Omron CX-Programmer project NewProject (CX-Programmer 6.11)

# PLC Elevator: CPM1(CPM1A) CPU20

## Global symbols (name address type ; comment)
Button_1 200.07 BOOL  ; Call Button 1st
Button_2 200.06 BOOL  ; Call Button 2nd
Button_3 200.05 BOOL  ; Call Button 3rd
Button_4 200.04 BOOL  ; Call Button 4th
Button_Dn 200.09 BOOL  ; Manual Down
Button_Up 200.08 BOOL  ; Manual Up
Fault_Initialize 211.00 BOOL  ; Fault - Initialize
Fault_Motor_Down 211.02 BOOL  ; Fault - Motor Down
Fault_Motor_Up 211.01 BOOL  ; Fault - Motor Up
Fault_Reset_Bit 208.00 BOOL  ; Fault Reset Bit
Floor_Number 220 CHANNEL  ; Current Floor Number
HMI_IO_PC 232 CHANNEL L  ; HMI IO From SCADA (PC)
HMI_IO_PLC 231 CHANNEL L  ; HMI IO From PLC
HMI_I_BTN1 233.00 BOOL L  ; HMI SCADA - 1st Floor Button
HMI_I_BTN2 233.01 BOOL L  ; HMI SCADA - 2nd Floor Button
HMI_I_BTN3 233.02 BOOL L  ; HMI SCADA - 3rd Floor Button
HMI_I_BTN4 233.03 BOOL L  ; HMI SCADA - 4th Floor Button
HMI_I_MAND 233.05 BOOL L  ; HMI SCADA - Manual Down Button
HMI_I_MANU 233.04 BOOL L  ; HMI SCADA - Manual Up Button
HMI_O_Down 233.07 BOOL L  ; HMI SCADA - Down Motor Running
HMI_O_Up 233.06 BOOL L  ; HMI SCADA - Up Motor Running
HMI_Step 230 CHANNEL L  ; HMI Step String
I_00 0.00 BOOL  ; GN Start - 4th
I_01 0.01 BOOL  ; BK Start - 3rd
I_02 0.02 BOOL  ; BK Jog - 2nd
I_03 0.03 BOOL  ; RD EStop - 1st
I_04 0.04 BOOL  ; RD Stop - UP
I_05 0.05 BOOL  ; RD Stop - DN
I_07 0.07 BOOL  ; Basement
I_08 0.08 BOOL  ; Level 1
I_09 0.09 BOOL  ; Level 4
I_10 0.10 BOOL  ; Level 3
I_11 0.11 BOOL  ; Level 2
LS_Basement 200.10 BOOL  ; Elevator @ Basement
LS_Level1 200.00 BOOL  ; Elevator @ Level 1
LS_Level2 200.01 BOOL  ; Elevator @ Level 2
LS_Level3 200.02 BOOL  ; Elevator @ Level 3
LS_Level4 200.03 BOOL  ; Elevator @ Level 4
O_01 10.01 BOOL  ; Up Motor
O_02 10.02 BOOL  ; Down Motor
Req_Floor 221 CHANNEL  ; Request Floor
Run_Motor_Down_15 210.03 BOOL  ; Run Down Motor (S15)
Run_Motor_Down_2 210.01 BOOL  ; Run Down Motor (S2)
Run_Motor_Down_30 210.05 BOOL  ; Run Down Motor (S30)
Run_Motor_Up_12 210.00 BOOL  ; Run Up Motor (S12)
Run_Motor_Up_20 210.02 BOOL  ; Run Up Motor (S20)
S_02 202.00 BOOL  ; Step S02
S_03 202.01 BOOL  ; Step S03
S_04 202.02 BOOL  ; Step S04
S_05 202.03 BOOL  ; Step S05
S_06 202.04 BOOL  ; Step S06
S_07 202.05 BOOL  ; Step S07
S_10 202.06 BOOL  ; Step S10
S_11 202.07 BOOL  ; Step S11
S_120 202.08 BOOL  ; Step S120
S_121 202.09 BOOL  ; Step S121
S_122 202.10 BOOL  ; Step S122
S_123 202.11 BOOL  ; Step S123
S_124 202.12 BOOL  ; Step S124
S_150 204.05 BOOL  ; Step S150
S_151 204.06 BOOL  ; Step S151
S_152 204.07 BOOL  ; Step S152
S_153 204.08 BOOL  ; Step S153
S_154 204.09 BOOL  ; Step S154
S_20 204.02 BOOL  ; Step S20
S_30 204.03 BOOL  ; Step S30
S_60 206.00 BOOL  ; Initialize Fault Timer
S_65 206.01 BOOL  ; Motor Up Fault Timer
S_70 206.02 BOOL  ; Motor Down Fault Timer
S_75 206.03 BOOL  ; Manual Up Fault Timer
S_80 206.04 BOOL  ; Manual Down Fault Timer
T_00 201.00 BOOL  ; Transition T00
T_02A 201.01 BOOL  ; Transition T02A
T_02B 201.02 BOOL  ; Transition T02B
T_02C 201.03 BOOL  ; Transition T02C
T_02D 201.04 BOOL  ; Transition T02D
T_02E 201.05 BOOL  ; Transition T02E
T_02F 201.06 BOOL  ; Transition T02F
T_03A 201.07 BOOL  ; Transition T03A
T_03B 201.08 BOOL  ; Transition T03B
T_03C 201.09 BOOL  ; Transition T03C
T_03D 201.10 BOOL  ; Transition T03D
T_03E 201.11 BOOL  ; Transition T03E
T_10A 203.00 BOOL  ; Transition T10A
T_10B 203.01 BOOL  ; Transition T10B
T_10C 203.02 BOOL  ; Transition T10C
T_11A 203.03 BOOL  ; Transition T11A
T_11B 203.04 BOOL  ; Transition T11B
T_12 203.05 BOOL  ; Transition T12
T_12A 203.06 BOOL  ; Transition T12A
T_12A1 203.07 BOOL  ; Transition T12A1
T_12B 203.08 BOOL  ; Transition T12B
T_12B1 203.09 BOOL  ; Transition T12B1
T_12C 203.10 BOOL  ; Transition T12C
T_12C1 203.11 BOOL  ; Transition T12C1
T_12D 203.12 BOOL  ; Transition T12D
T_12D1 203.13 BOOL  ; Transition T12D1
T_12E 203.14 BOOL  ; Transition T12E
T_15 209.00 BOOL  ; Transition T15
T_15A 209.01 BOOL  ; Transition T15A
T_15A1 209.02 BOOL  ; Transition T15A1
T_15B 209.03 BOOL  ; Transition T15B
T_15B1 209.04 BOOL  ; Transition T15B1
T_15C 209.05 BOOL  ; Transition T15C
T_15C1 209.06 BOOL  ; Transition T15C1
T_15D 209.07 BOOL  ; Transition T15D
T_15D1 209.08 BOOL  ; Transition T15D1
T_15E 209.09 BOOL  ; Transition T15E
T_20A 205.00 BOOL  ; Transition T20A
T_20B 205.01 BOOL  ; Transition T20B
T_20C 205.02 BOOL  ; Transition T20C
T_20D 205.03 BOOL  ; Transition T20D
T_20E 205.04 BOOL  ; Transition T20E
T_30A 205.05 BOOL  ; Transition T30A
T_30B 205.06 BOOL  ; Transition T30B
T_30C 205.07 BOOL  ; Transition T30C
T_30D 205.08 BOOL  ; Transition T30D
T_30E 205.09 BOOL  ; Transition T30E
T_60 207.00 BOOL  ; Transition T60
T_65 207.01 BOOL  ; Transition T65
T_70 207.02 BOOL  ; Transition T70
T_75 207.03 BOOL  ; Transition T75
T_80 207.04 BOOL  ; Transition T80
Timer_Flt_Dn TIM003 BOOL  ; Motor Down Fault
Timer_Flt_Init TIM001 BOOL  ; Initialization Fault Timer
Timer_Flt_Man_Down TIM006 BOOL  ; Manual Down Fault
Timer_Flt_Man_Up TIM004 BOOL  ; Manual Up Fault
Timer_Flt_Up TIM002 BOOL  ; Motor Up Fault
Timer_Running20 TIM005 BOOL  ; Running Timer (S20)
Timer_Running30 TIM007 BOOL  ; Running Timer (S30)

## Program Elevator (no task)

### Section Transistions

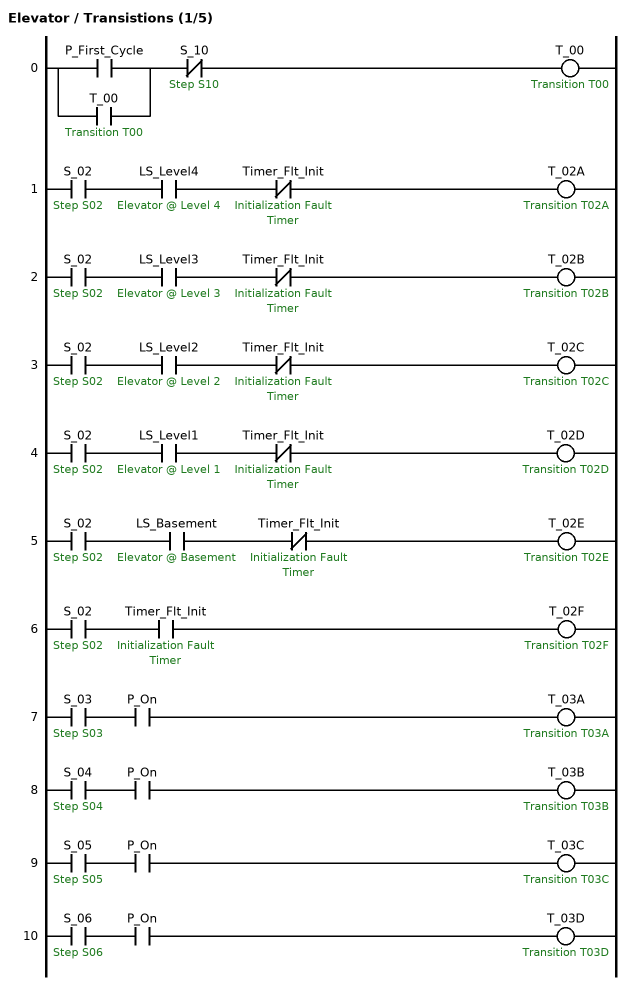
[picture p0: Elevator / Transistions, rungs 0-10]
; rung 0
LD P_First_Cycle
OR T_00  ; Transition T00
ANDNOT S_10  ; Step S10
OUT T_00  ; Transition T00
; rung 1
LD S_02  ; Step S02
AND LS_Level4  ; Elevator @ Level 4
ANDNOT Timer_Flt_Init  ; Initialization Fault Timer
OUT T_02A  ; Transition T02A
; rung 2
LD S_02  ; Step S02
AND LS_Level3  ; Elevator @ Level 3
ANDNOT Timer_Flt_Init  ; Initialization Fault Timer
OUT T_02B  ; Transition T02B
; rung 3
LD S_02  ; Step S02
AND LS_Level2  ; Elevator @ Level 2
ANDNOT Timer_Flt_Init  ; Initialization Fault Timer
OUT T_02C  ; Transition T02C
; rung 4
LD S_02  ; Step S02
AND LS_Level1  ; Elevator @ Level 1
ANDNOT Timer_Flt_Init  ; Initialization Fault Timer
OUT T_02D  ; Transition T02D
; rung 5
LD S_02  ; Step S02
AND LS_Basement  ; Elevator @ Basement
ANDNOT Timer_Flt_Init  ; Initialization Fault Timer
OUT T_02E  ; Transition T02E
; rung 6
LD S_02  ; Step S02
AND Timer_Flt_Init  ; Initialization Fault Timer
OUT T_02F  ; Transition T02F
; rung 7
LD S_03  ; Step S03
AND P_On
OUT T_03A  ; Transition T03A
; rung 8
LD S_04  ; Step S04
AND P_On
OUT T_03B  ; Transition T03B
; rung 9
LD S_05  ; Step S05
AND P_On
OUT T_03C  ; Transition T03C
; rung 10
LD S_06  ; Step S06
AND P_On
OUT T_03D  ; Transition T03D

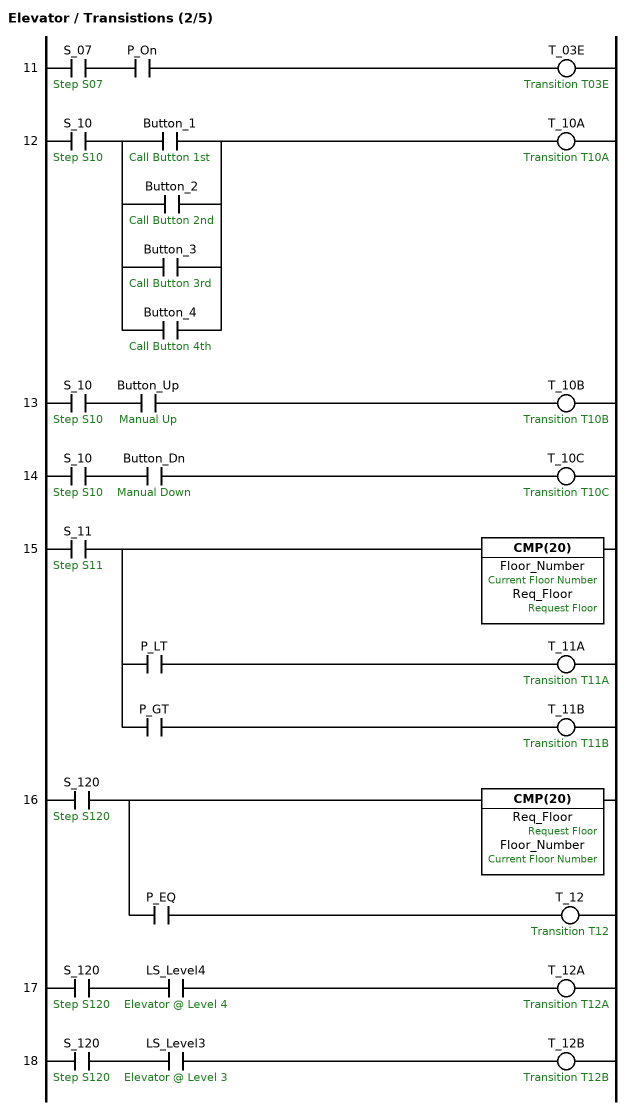
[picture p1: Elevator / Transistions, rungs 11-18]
; rung 11
LD S_07  ; Step S07
AND P_On
OUT T_03E  ; Transition T03E
; rung 12
LD S_10  ; Step S10
LD Button_1  ; Call Button 1st
OR Button_2  ; Call Button 2nd
OR Button_3  ; Call Button 3rd
OR Button_4  ; Call Button 4th
ANDLD
OUT T_10A  ; Transition T10A
; rung 13
LD S_10  ; Step S10
AND Button_Up  ; Manual Up
OUT T_10B  ; Transition T10B
; rung 14
LD S_10  ; Step S10
AND Button_Dn  ; Manual Down
OUT T_10C  ; Transition T10C
; rung 15
LD S_11  ; Step S11
OUT TR0
CMP(20) Floor_Number Req_Floor  ; Current Floor Number, Request Floor
AND P_LT
OUT T_11A  ; Transition T11A
LD TR0
AND P_GT
OUT T_11B  ; Transition T11B
; rung 16
LD S_120  ; Step S120
CMP(20) Req_Floor Floor_Number  ; Request Floor, Current Floor Number
AND P_EQ
OUT T_12  ; Transition T12
; rung 17
LD S_120  ; Step S120
AND LS_Level4  ; Elevator @ Level 4
OUT T_12A  ; Transition T12A
; rung 18
LD S_120  ; Step S120
AND LS_Level3  ; Elevator @ Level 3
OUT T_12B  ; Transition T12B

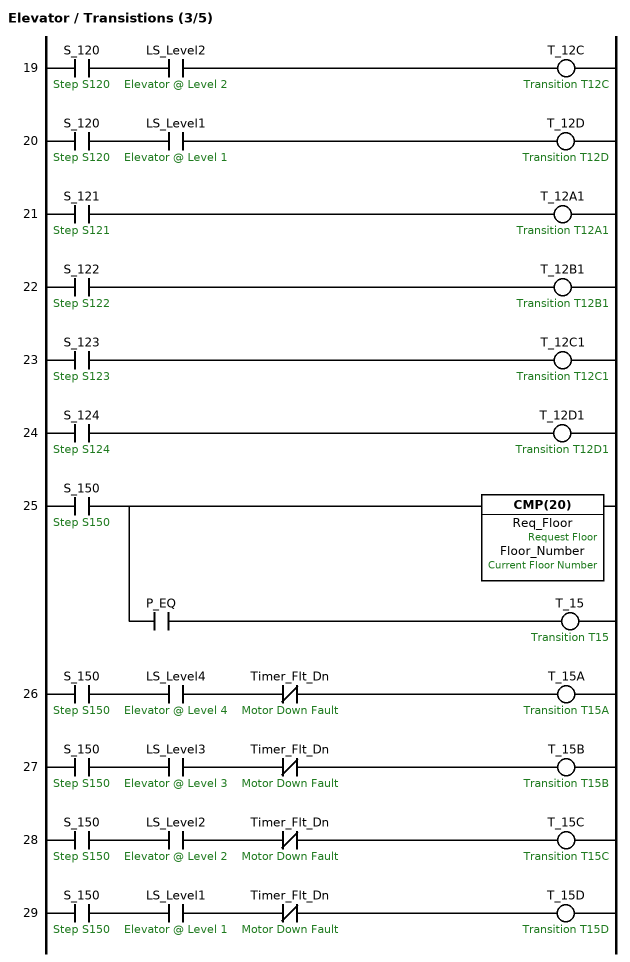
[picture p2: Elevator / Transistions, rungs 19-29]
; rung 19
LD S_120  ; Step S120
AND LS_Level2  ; Elevator @ Level 2
OUT T_12C  ; Transition T12C
; rung 20
LD S_120  ; Step S120
AND LS_Level1  ; Elevator @ Level 1
OUT T_12D  ; Transition T12D
; rung 21
LD S_121  ; Step S121
OUT T_12A1  ; Transition T12A1
; rung 22
LD S_122  ; Step S122
OUT T_12B1  ; Transition T12B1
; rung 23
LD S_123  ; Step S123
OUT T_12C1  ; Transition T12C1
; rung 24
LD S_124  ; Step S124
OUT T_12D1  ; Transition T12D1
; rung 25
LD S_150  ; Step S150
CMP(20) Req_Floor Floor_Number  ; Request Floor, Current Floor Number
AND P_EQ
OUT T_15  ; Transition T15
; rung 26
LD S_150  ; Step S150
AND LS_Level4  ; Elevator @ Level 4
ANDNOT Timer_Flt_Dn  ; Motor Down Fault
OUT T_15A  ; Transition T15A
; rung 27
LD S_150  ; Step S150
AND LS_Level3  ; Elevator @ Level 3
ANDNOT Timer_Flt_Dn  ; Motor Down Fault
OUT T_15B  ; Transition T15B
; rung 28
LD S_150  ; Step S150
AND LS_Level2  ; Elevator @ Level 2
ANDNOT Timer_Flt_Dn  ; Motor Down Fault
OUT T_15C  ; Transition T15C
; rung 29
LD S_150  ; Step S150
AND LS_Level1  ; Elevator @ Level 1
ANDNOT Timer_Flt_Dn  ; Motor Down Fault
OUT T_15D  ; Transition T15D

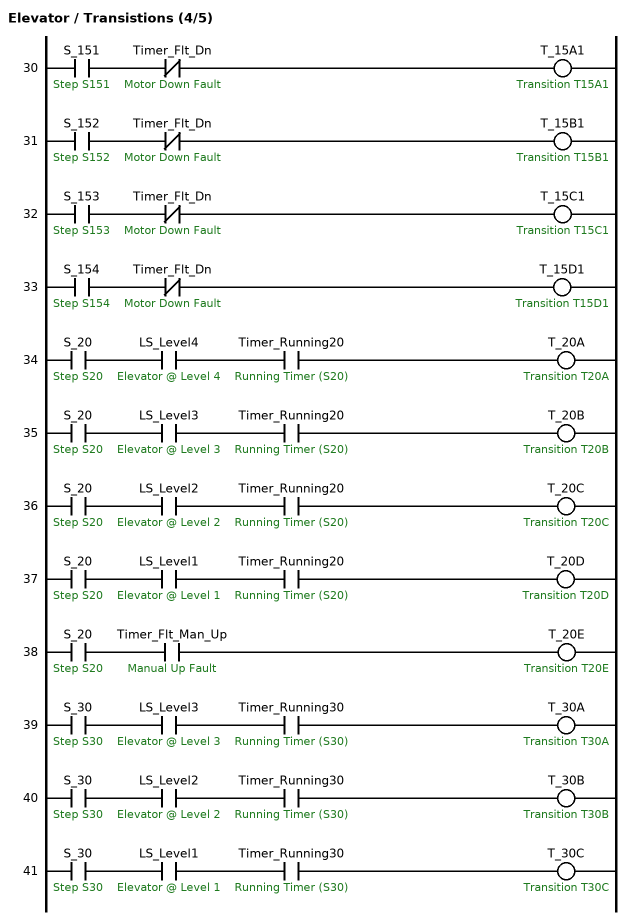
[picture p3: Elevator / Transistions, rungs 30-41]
; rung 30
LD S_151  ; Step S151
ANDNOT Timer_Flt_Dn  ; Motor Down Fault
OUT T_15A1  ; Transition T15A1
; rung 31
LD S_152  ; Step S152
ANDNOT Timer_Flt_Dn  ; Motor Down Fault
OUT T_15B1  ; Transition T15B1
; rung 32
LD S_153  ; Step S153
ANDNOT Timer_Flt_Dn  ; Motor Down Fault
OUT T_15C1  ; Transition T15C1
; rung 33
LD S_154  ; Step S154
ANDNOT Timer_Flt_Dn  ; Motor Down Fault
OUT T_15D1  ; Transition T15D1
; rung 34
LD S_20  ; Step S20
AND LS_Level4  ; Elevator @ Level 4
AND Timer_Running20  ; Running Timer (S20)
OUT T_20A  ; Transition T20A
; rung 35
LD S_20  ; Step S20
AND LS_Level3  ; Elevator @ Level 3
AND Timer_Running20  ; Running Timer (S20)
OUT T_20B  ; Transition T20B
; rung 36
LD S_20  ; Step S20
AND LS_Level2  ; Elevator @ Level 2
AND Timer_Running20  ; Running Timer (S20)
OUT T_20C  ; Transition T20C
; rung 37
LD S_20  ; Step S20
AND LS_Level1  ; Elevator @ Level 1
AND Timer_Running20  ; Running Timer (S20)
OUT T_20D  ; Transition T20D
; rung 38
LD S_20  ; Step S20
AND Timer_Flt_Man_Up  ; Manual Up Fault
OUT T_20E  ; Transition T20E
; rung 39
LD S_30  ; Step S30
AND LS_Level3  ; Elevator @ Level 3
AND Timer_Running30  ; Running Timer (S30)
OUT T_30A  ; Transition T30A
; rung 40
LD S_30  ; Step S30
AND LS_Level2  ; Elevator @ Level 2
AND Timer_Running30  ; Running Timer (S30)
OUT T_30B  ; Transition T30B
; rung 41
LD S_30  ; Step S30
AND LS_Level1  ; Elevator @ Level 1
AND Timer_Running30  ; Running Timer (S30)
OUT T_30C  ; Transition T30C

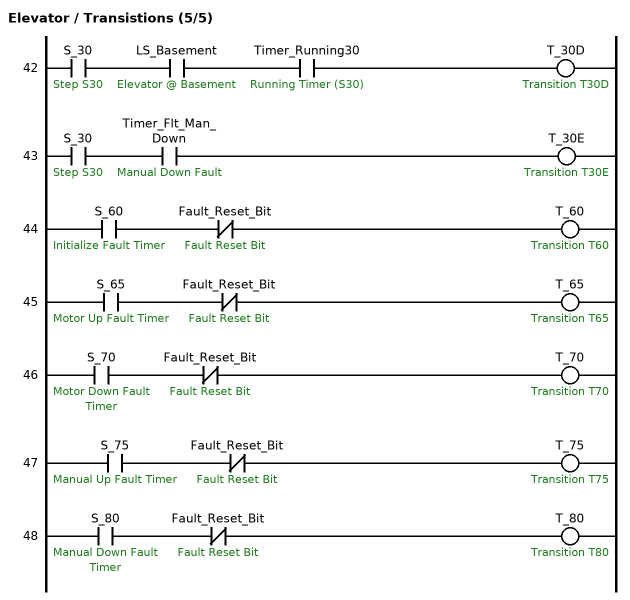
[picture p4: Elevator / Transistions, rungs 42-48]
; rung 42
LD S_30  ; Step S30
AND LS_Basement  ; Elevator @ Basement
AND Timer_Running30  ; Running Timer (S30)
OUT T_30D  ; Transition T30D
; rung 43
LD S_30  ; Step S30
AND Timer_Flt_Man_Down  ; Manual Down Fault
OUT T_30E  ; Transition T30E
; rung 44
LD S_60  ; Initialize Fault Timer
ANDNOT Fault_Reset_Bit  ; Fault Reset Bit
OUT T_60  ; Transition T60
; rung 45
LD S_65  ; Motor Up Fault Timer
ANDNOT Fault_Reset_Bit  ; Fault Reset Bit
OUT T_65  ; Transition T65
; rung 46
LD S_70  ; Motor Down Fault Timer
ANDNOT Fault_Reset_Bit  ; Fault Reset Bit
OUT T_70  ; Transition T70
; rung 47
LD S_75  ; Manual Up Fault Timer
ANDNOT Fault_Reset_Bit  ; Fault Reset Bit
OUT T_75  ; Transition T75
; rung 48
LD S_80  ; Manual Down Fault Timer
ANDNOT Fault_Reset_Bit  ; Fault Reset Bit
OUT T_80  ; Transition T80

### Section StepIterator

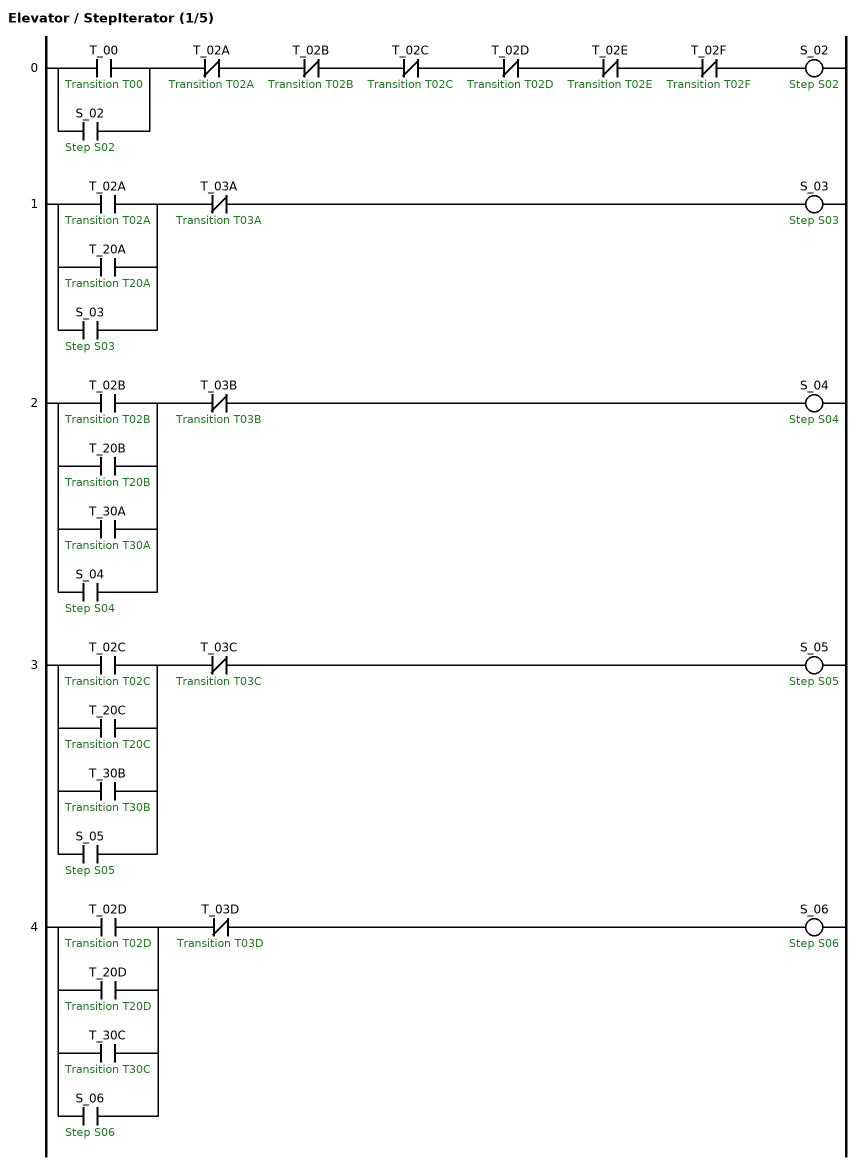
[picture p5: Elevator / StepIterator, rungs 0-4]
; rung 0
LD T_00  ; Transition T00
OR S_02  ; Step S02
ANDNOT T_02A  ; Transition T02A
ANDNOT T_02B  ; Transition T02B
ANDNOT T_02C  ; Transition T02C
ANDNOT T_02D  ; Transition T02D
ANDNOT T_02E  ; Transition T02E
ANDNOT T_02F  ; Transition T02F
OUT S_02  ; Step S02
; rung 1
LD T_02A  ; Transition T02A
OR T_20A  ; Transition T20A
OR S_03  ; Step S03
ANDNOT T_03A  ; Transition T03A
OUT S_03  ; Step S03
; rung 2
LD T_02B  ; Transition T02B
OR T_20B  ; Transition T20B
OR T_30A  ; Transition T30A
OR S_04  ; Step S04
ANDNOT T_03B  ; Transition T03B
OUT S_04  ; Step S04
; rung 3
LD T_02C  ; Transition T02C
OR T_20C  ; Transition T20C
OR T_30B  ; Transition T30B
OR S_05  ; Step S05
ANDNOT T_03C  ; Transition T03C
OUT S_05  ; Step S05
; rung 4
LD T_02D  ; Transition T02D
OR T_20D  ; Transition T20D
OR T_30C  ; Transition T30C
OR S_06  ; Step S06
ANDNOT T_03D  ; Transition T03D
OUT S_06  ; Step S06

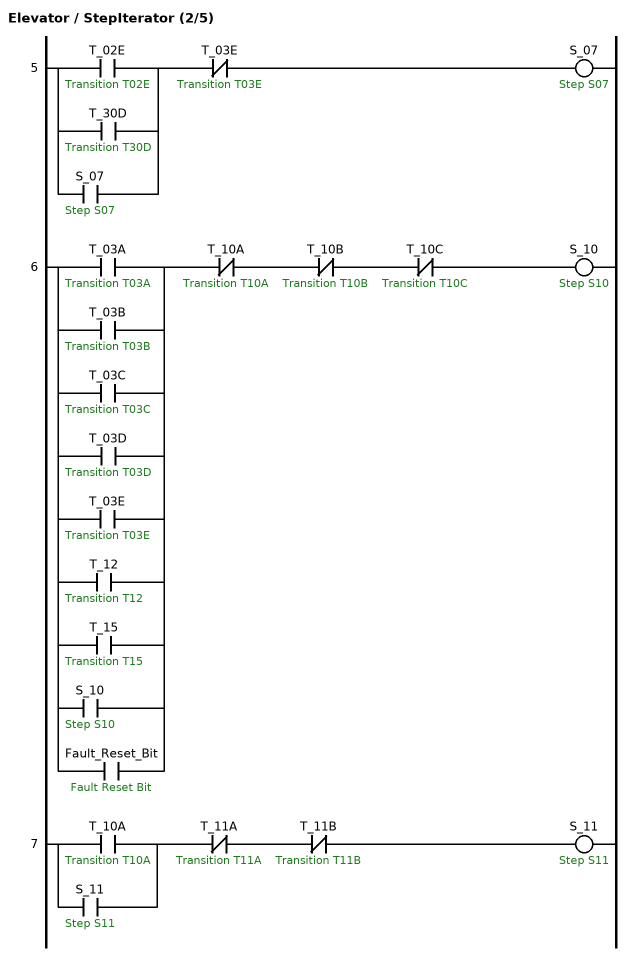
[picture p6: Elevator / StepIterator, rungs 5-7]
; rung 5
LD T_02E  ; Transition T02E
OR T_30D  ; Transition T30D
OR S_07  ; Step S07
ANDNOT T_03E  ; Transition T03E
OUT S_07  ; Step S07
; rung 6
LD T_03A  ; Transition T03A
OR T_03B  ; Transition T03B
OR T_03C  ; Transition T03C
OR T_03D  ; Transition T03D
OR T_03E  ; Transition T03E
OR T_12  ; Transition T12
OR T_15  ; Transition T15
OR S_10  ; Step S10
OR Fault_Reset_Bit  ; Fault Reset Bit
ANDNOT T_10A  ; Transition T10A
ANDNOT T_10B  ; Transition T10B
ANDNOT T_10C  ; Transition T10C
OUT S_10  ; Step S10
; rung 7
LD T_10A  ; Transition T10A
OR S_11  ; Step S11
ANDNOT T_11A  ; Transition T11A
ANDNOT T_11B  ; Transition T11B
OUT S_11  ; Step S11

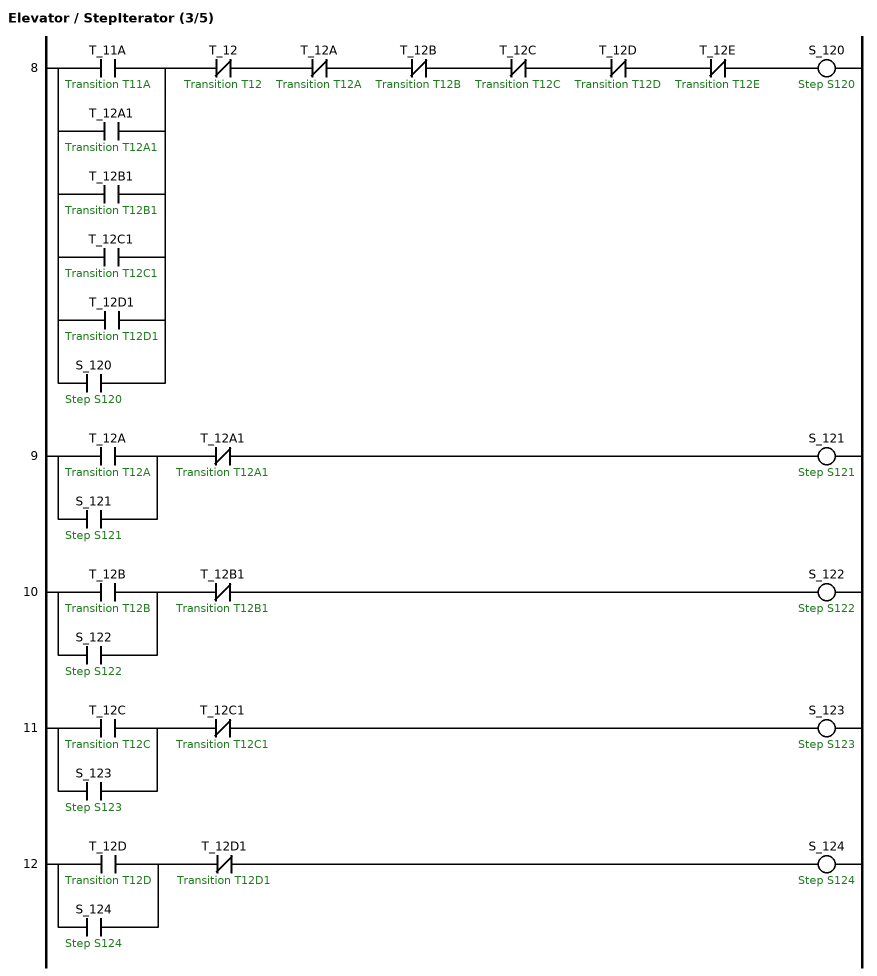
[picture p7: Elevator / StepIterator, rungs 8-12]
; rung 8
LD T_11A  ; Transition T11A
OR T_12A1  ; Transition T12A1
OR T_12B1  ; Transition T12B1
OR T_12C1  ; Transition T12C1
OR T_12D1  ; Transition T12D1
OR S_120  ; Step S120
ANDNOT T_12  ; Transition T12
ANDNOT T_12A  ; Transition T12A
ANDNOT T_12B  ; Transition T12B
ANDNOT T_12C  ; Transition T12C
ANDNOT T_12D  ; Transition T12D
ANDNOT T_12E  ; Transition T12E
OUT S_120  ; Step S120
; rung 9
LD T_12A  ; Transition T12A
OR S_121  ; Step S121
ANDNOT T_12A1  ; Transition T12A1
OUT S_121  ; Step S121
; rung 10
LD T_12B  ; Transition T12B
OR S_122  ; Step S122
ANDNOT T_12B1  ; Transition T12B1
OUT S_122  ; Step S122
; rung 11
LD T_12C  ; Transition T12C
OR S_123  ; Step S123
ANDNOT T_12C1  ; Transition T12C1
OUT S_123  ; Step S123
; rung 12
LD T_12D  ; Transition T12D
OR S_124  ; Step S124
ANDNOT T_12D1  ; Transition T12D1
OUT S_124  ; Step S124

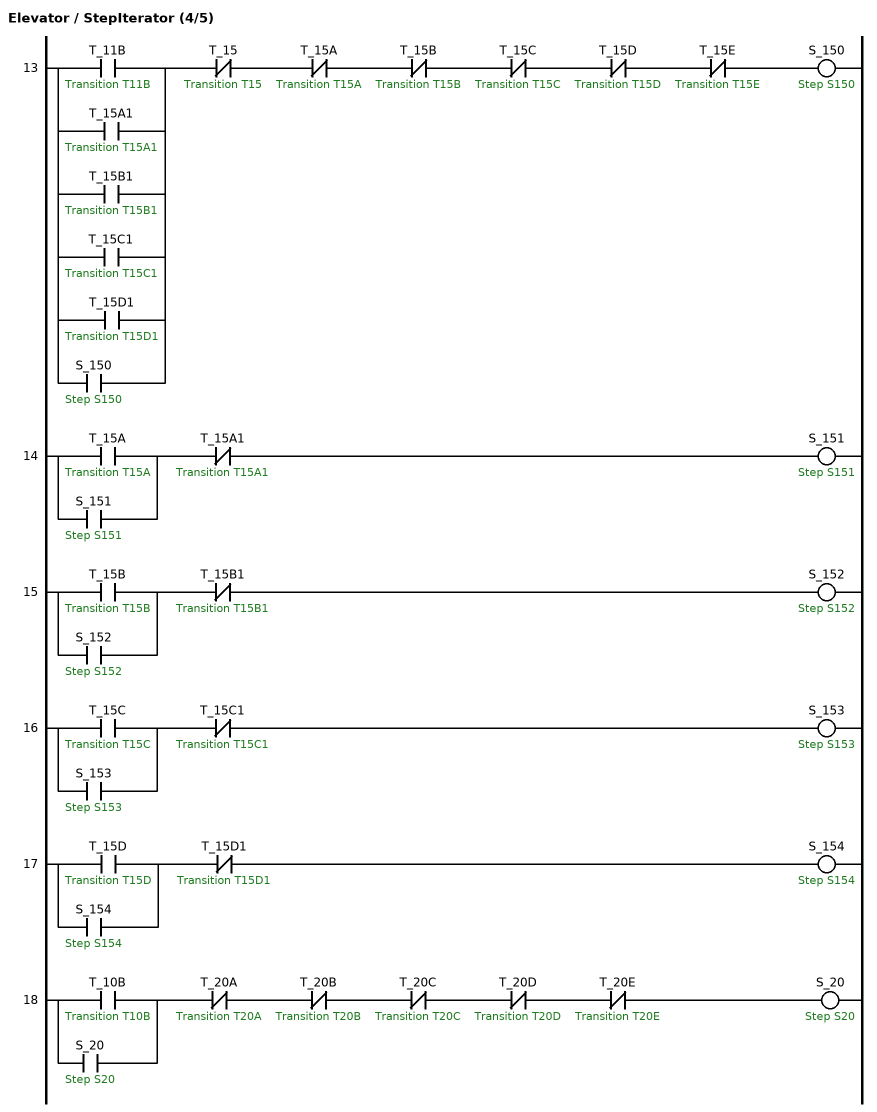
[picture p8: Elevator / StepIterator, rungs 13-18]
; rung 13
LD T_11B  ; Transition T11B
OR T_15A1  ; Transition T15A1
OR T_15B1  ; Transition T15B1
OR T_15C1  ; Transition T15C1
OR T_15D1  ; Transition T15D1
OR S_150  ; Step S150
ANDNOT T_15  ; Transition T15
ANDNOT T_15A  ; Transition T15A
ANDNOT T_15B  ; Transition T15B
ANDNOT T_15C  ; Transition T15C
ANDNOT T_15D  ; Transition T15D
ANDNOT T_15E  ; Transition T15E
OUT S_150  ; Step S150
; rung 14
LD T_15A  ; Transition T15A
OR S_151  ; Step S151
ANDNOT T_15A1  ; Transition T15A1
OUT S_151  ; Step S151
; rung 15
LD T_15B  ; Transition T15B
OR S_152  ; Step S152
ANDNOT T_15B1  ; Transition T15B1
OUT S_152  ; Step S152
; rung 16
LD T_15C  ; Transition T15C
OR S_153  ; Step S153
ANDNOT T_15C1  ; Transition T15C1
OUT S_153  ; Step S153
; rung 17
LD T_15D  ; Transition T15D
OR S_154  ; Step S154
ANDNOT T_15D1  ; Transition T15D1
OUT S_154  ; Step S154
; rung 18
LD T_10B  ; Transition T10B
OR S_20  ; Step S20
ANDNOT T_20A  ; Transition T20A
ANDNOT T_20B  ; Transition T20B
ANDNOT T_20C  ; Transition T20C
ANDNOT T_20D  ; Transition T20D
ANDNOT T_20E  ; Transition T20E
OUT S_20  ; Step S20

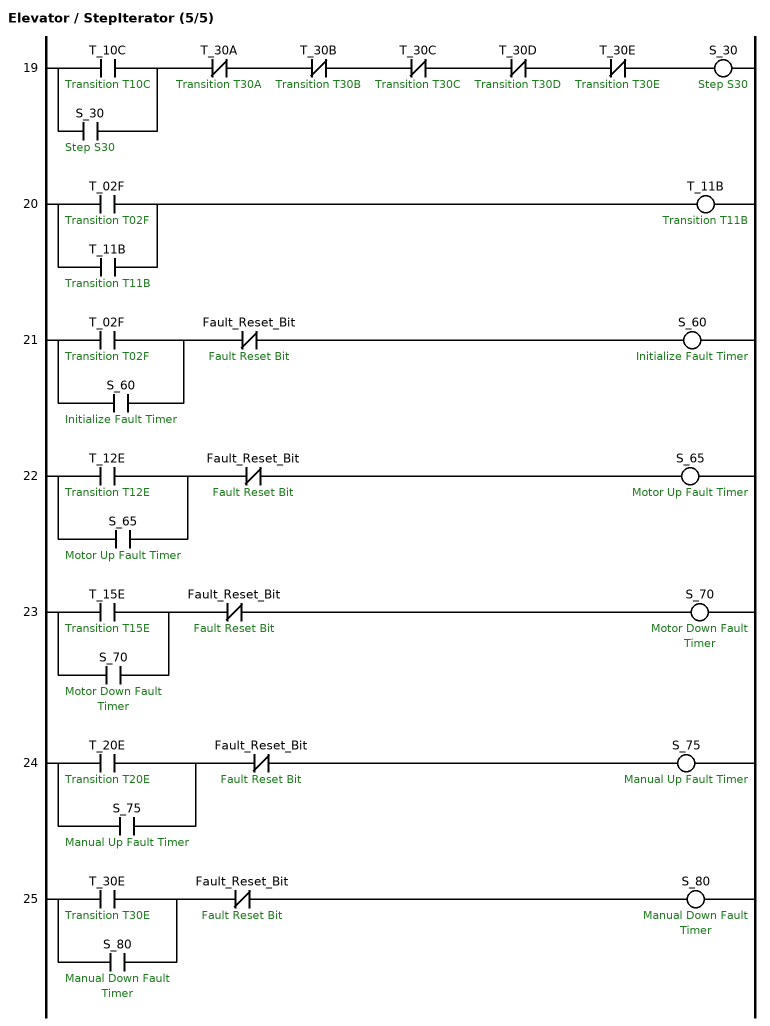
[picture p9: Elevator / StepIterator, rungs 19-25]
; rung 19
LD T_10C  ; Transition T10C
OR S_30  ; Step S30
ANDNOT T_30A  ; Transition T30A
ANDNOT T_30B  ; Transition T30B
ANDNOT T_30C  ; Transition T30C
ANDNOT T_30D  ; Transition T30D
ANDNOT T_30E  ; Transition T30E
OUT S_30  ; Step S30
; rung 20
LD T_02F  ; Transition T02F
OR T_11B  ; Transition T11B
OUT T_11B  ; Transition T11B
; rung 21
LD T_02F  ; Transition T02F
OR S_60  ; Initialize Fault Timer
ANDNOT Fault_Reset_Bit  ; Fault Reset Bit
OUT S_60  ; Initialize Fault Timer
; rung 22
LD T_12E  ; Transition T12E
OR S_65  ; Motor Up Fault Timer
ANDNOT Fault_Reset_Bit  ; Fault Reset Bit
OUT S_65  ; Motor Up Fault Timer
; rung 23
LD T_15E  ; Transition T15E
OR S_70  ; Motor Down Fault Timer
ANDNOT Fault_Reset_Bit  ; Fault Reset Bit
OUT S_70  ; Motor Down Fault Timer
; rung 24
LD T_20E  ; Transition T20E
OR S_75  ; Manual Up Fault Timer
ANDNOT Fault_Reset_Bit  ; Fault Reset Bit
OUT S_75  ; Manual Up Fault Timer
; rung 25
LD T_30E  ; Transition T30E
OR S_80  ; Manual Down Fault Timer
ANDNOT Fault_Reset_Bit  ; Fault Reset Bit
OUT S_80  ; Manual Down Fault Timer

### Section Steps

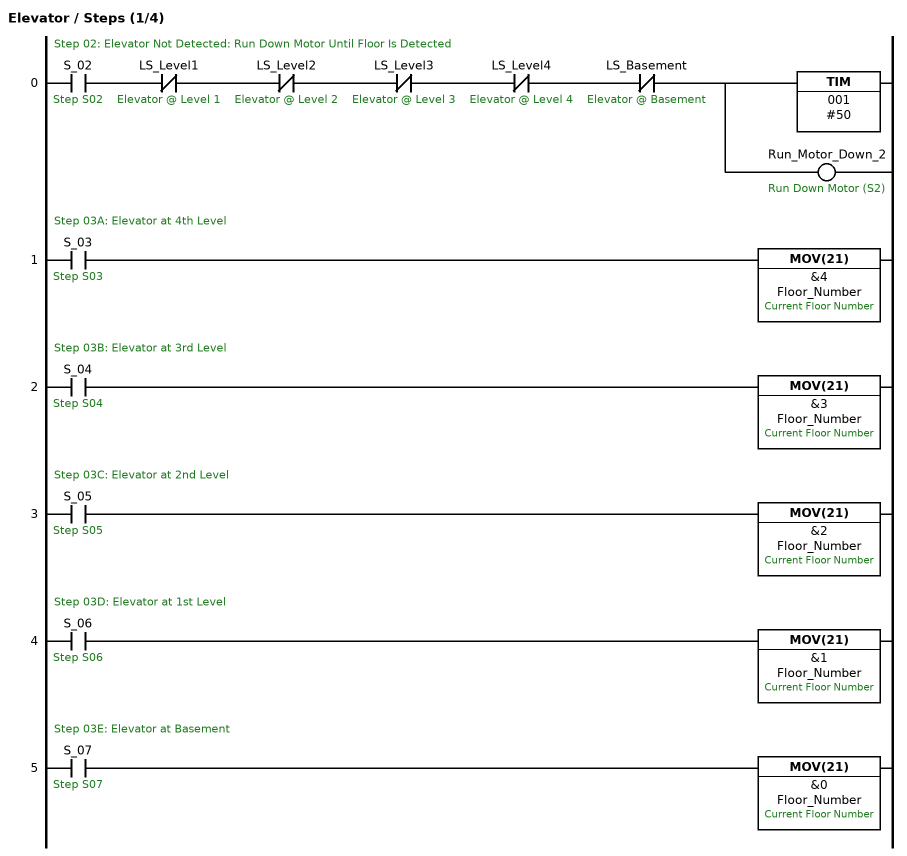
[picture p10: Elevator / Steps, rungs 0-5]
; rung 0: Step 02: Elevator Not Detected: Run Down Motor Until Floor Is Detected
LD S_02  ; Step S02
ANDNOT LS_Level1  ; Elevator @ Level 1
ANDNOT LS_Level2  ; Elevator @ Level 2
ANDNOT LS_Level3  ; Elevator @ Level 3
ANDNOT LS_Level4  ; Elevator @ Level 4
ANDNOT LS_Basement  ; Elevator @ Basement
TIM 001 #50
OUT Run_Motor_Down_2  ; Run Down Motor (S2)
; rung 1: Step 03A: Elevator at 4th Level
LD S_03  ; Step S03
MOV(21) &4 Floor_Number  ; Current Floor Number
; rung 2: Step 03B: Elevator at 3rd Level
LD S_04  ; Step S04
MOV(21) &3 Floor_Number  ; Current Floor Number
; rung 3: Step 03C: Elevator at 2nd Level
LD S_05  ; Step S05
MOV(21) &2 Floor_Number  ; Current Floor Number
; rung 4: Step 03D: Elevator at 1st Level
LD S_06  ; Step S06
MOV(21) &1 Floor_Number  ; Current Floor Number
; rung 5: Step 03E: Elevator at Basement
LD S_07  ; Step S07
MOV(21) &0 Floor_Number  ; Current Floor Number
; rung 6: Step 10: Wait for Call

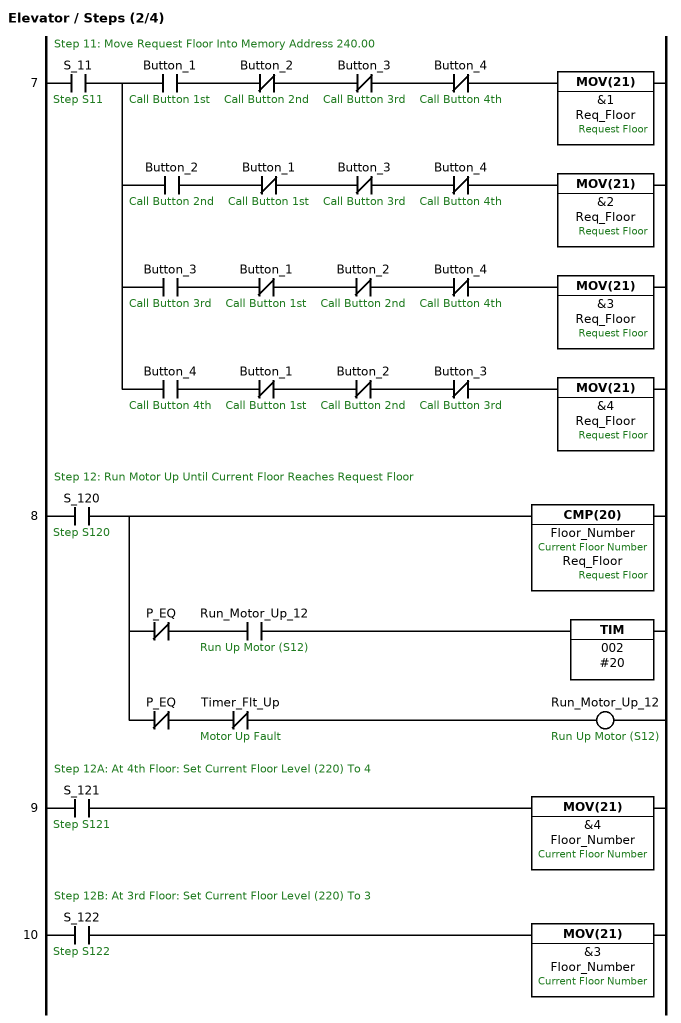
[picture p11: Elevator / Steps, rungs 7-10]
; rung 7: Step 11: Move Request Floor Into Memory Address 240.00
LD S_11  ; Step S11
OUT TR0
AND Button_1  ; Call Button 1st
ANDNOT Button_2  ; Call Button 2nd
ANDNOT Button_3  ; Call Button 3rd
ANDNOT Button_4  ; Call Button 4th
MOV(21) &1 Req_Floor  ; Request Floor
LD TR0
AND Button_2  ; Call Button 2nd
ANDNOT Button_1  ; Call Button 1st
ANDNOT Button_3  ; Call Button 3rd
ANDNOT Button_4  ; Call Button 4th
MOV(21) &2 Req_Floor  ; Request Floor
LD TR0
AND Button_3  ; Call Button 3rd
ANDNOT Button_1  ; Call Button 1st
ANDNOT Button_2  ; Call Button 2nd
ANDNOT Button_4  ; Call Button 4th
MOV(21) &3 Req_Floor  ; Request Floor
LD TR0
AND Button_4  ; Call Button 4th
ANDNOT Button_1  ; Call Button 1st
ANDNOT Button_2  ; Call Button 2nd
ANDNOT Button_3  ; Call Button 3rd
MOV(21) &4 Req_Floor  ; Request Floor
; rung 8: Step 12: Run Motor Up Until Current Floor Reaches Request Floor
LD S_120  ; Step S120
OUT TR0
CMP(20) Floor_Number Req_Floor  ; Current Floor Number, Request Floor
ANDNOT P_EQ
AND Run_Motor_Up_12  ; Run Up Motor (S12)
TIM 002 #20
LD TR0
ANDNOT P_EQ
ANDNOT Timer_Flt_Up  ; Motor Up Fault
OUT Run_Motor_Up_12  ; Run Up Motor (S12)
; rung 9: Step 12A: At 4th Floor: Set Current Floor Level (220) To 4
LD S_121  ; Step S121
MOV(21) &4 Floor_Number  ; Current Floor Number
; rung 10: Step 12B: At 3rd Floor: Set Current Floor Level (220) To 3
LD S_122  ; Step S122
MOV(21) &3 Floor_Number  ; Current Floor Number

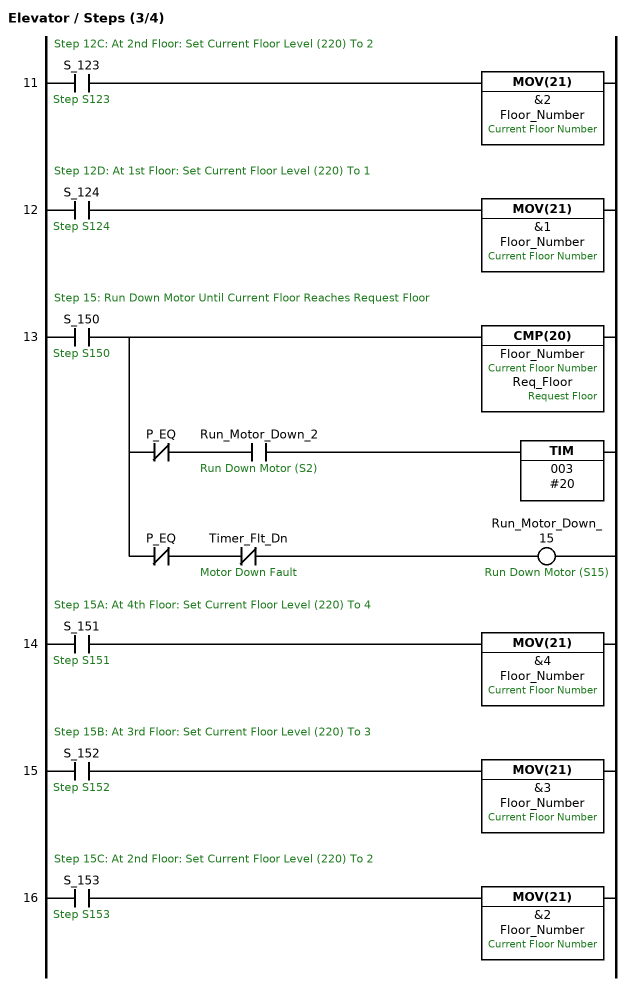
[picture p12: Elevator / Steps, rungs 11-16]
; rung 11: Step 12C: At 2nd Floor: Set Current Floor Level (220) To 2
LD S_123  ; Step S123
MOV(21) &2 Floor_Number  ; Current Floor Number
; rung 12: Step 12D: At 1st Floor: Set Current Floor Level (220) To 1
LD S_124  ; Step S124
MOV(21) &1 Floor_Number  ; Current Floor Number
; rung 13: Step 15: Run Down Motor Until Current Floor Reaches Request Floor
LD S_150  ; Step S150
OUT TR0
CMP(20) Floor_Number Req_Floor  ; Current Floor Number, Request Floor
ANDNOT P_EQ
AND Run_Motor_Down_2  ; Run Down Motor (S2)
TIM 003 #20
LD TR0
ANDNOT P_EQ
ANDNOT Timer_Flt_Dn  ; Motor Down Fault
OUT Run_Motor_Down_15  ; Run Down Motor (S15)
; rung 14: Step 15A: At 4th Floor: Set Current Floor Level (220) To 4
LD S_151  ; Step S151
MOV(21) &4 Floor_Number  ; Current Floor Number
; rung 15: Step 15B: At 3rd Floor: Set Current Floor Level (220) To 3
LD S_152  ; Step S152
MOV(21) &3 Floor_Number  ; Current Floor Number
; rung 16: Step 15C: At 2nd Floor: Set Current Floor Level (220) To 2
LD S_153  ; Step S153
MOV(21) &2 Floor_Number  ; Current Floor Number

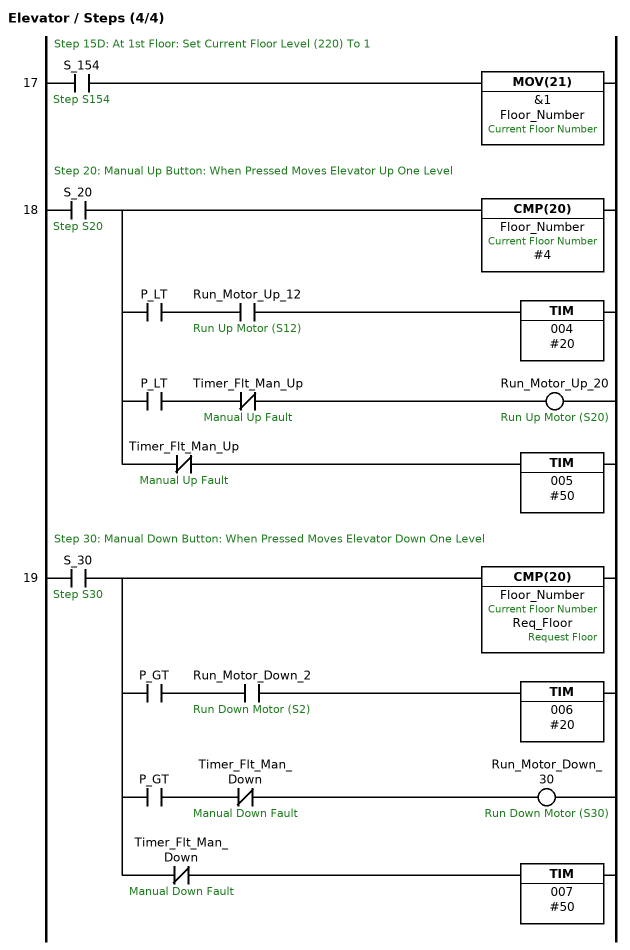
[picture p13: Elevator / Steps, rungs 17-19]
; rung 17: Step 15D: At 1st Floor: Set Current Floor Level (220) To 1
LD S_154  ; Step S154
MOV(21) &1 Floor_Number  ; Current Floor Number
; rung 18: Step 20: Manual Up Button: When Pressed Moves Elevator Up One Level
LD S_20  ; Step S20
OUT TR0
CMP(20) Floor_Number #4  ; Current Floor Number
AND P_LT
AND Run_Motor_Up_12  ; Run Up Motor (S12)
TIM 004 #20
LD TR0
AND P_LT
ANDNOT Timer_Flt_Man_Up  ; Manual Up Fault
OUT Run_Motor_Up_20  ; Run Up Motor (S20)
LD TR0
ANDNOT Timer_Flt_Man_Up  ; Manual Up Fault
TIM 005 #50
; rung 19: Step 30: Manual Down Button: When Pressed Moves Elevator Down One Level
LD S_30  ; Step S30
OUT TR0
CMP(20) Floor_Number Req_Floor  ; Current Floor Number, Request Floor
AND P_GT
AND Run_Motor_Down_2  ; Run Down Motor (S2)
TIM 006 #20
LD TR0
AND P_GT
ANDNOT Timer_Flt_Man_Down  ; Manual Down Fault
OUT Run_Motor_Down_30  ; Run Down Motor (S30)
LD TR0
ANDNOT Timer_Flt_Man_Down  ; Manual Down Fault
TIM 007 #50

### Section IO
; rung 1: Inputs

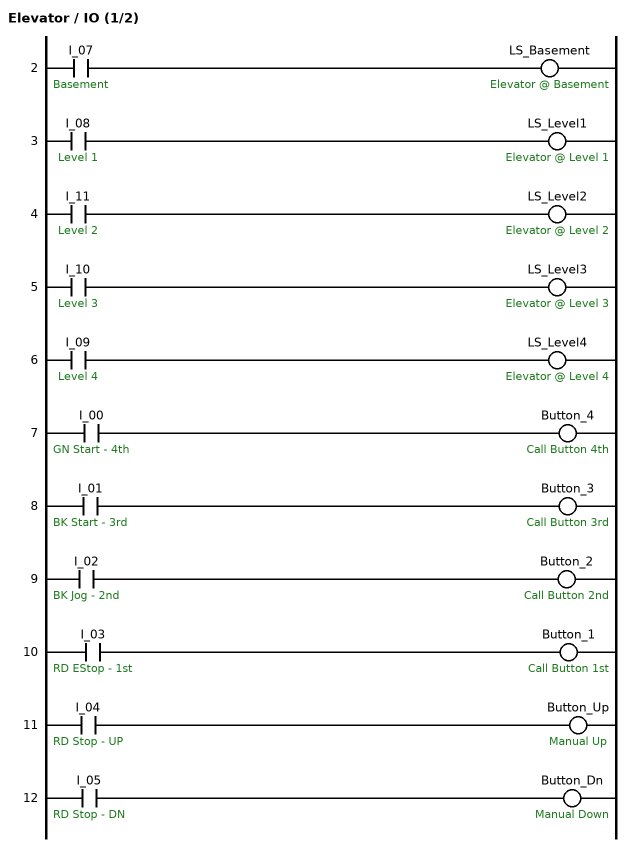
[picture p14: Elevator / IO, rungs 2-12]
; rung 2
LD I_07  ; Basement
OUT LS_Basement  ; Elevator @ Basement
; rung 3
LD I_08  ; Level 1
OUT LS_Level1  ; Elevator @ Level 1
; rung 4
LD I_11  ; Level 2
OUT LS_Level2  ; Elevator @ Level 2
; rung 5
LD I_10  ; Level 3
OUT LS_Level3  ; Elevator @ Level 3
; rung 6
LD I_09  ; Level 4
OUT LS_Level4  ; Elevator @ Level 4
; rung 7
LD I_00  ; GN Start - 4th
OUT Button_4  ; Call Button 4th
; rung 8
LD I_01  ; BK Start - 3rd
OUT Button_3  ; Call Button 3rd
; rung 9
LD I_02  ; BK Jog - 2nd
OUT Button_2  ; Call Button 2nd
; rung 10
LD I_03  ; RD EStop - 1st
OUT Button_1  ; Call Button 1st
; rung 11
LD I_04  ; RD Stop - UP
OUT Button_Up  ; Manual Up
; rung 12
LD I_05  ; RD Stop - DN
OUT Button_Dn  ; Manual Down
; rung 14: Outputs

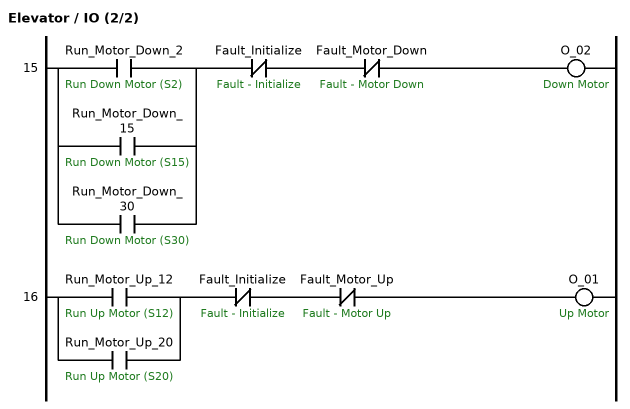
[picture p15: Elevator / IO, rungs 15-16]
; rung 15
LD Run_Motor_Down_2  ; Run Down Motor (S2)
OR Run_Motor_Down_15  ; Run Down Motor (S15)
OR Run_Motor_Down_30  ; Run Down Motor (S30)
ANDNOT Fault_Initialize  ; Fault - Initialize
ANDNOT Fault_Motor_Down  ; Fault - Motor Down
OUT O_02  ; Down Motor
; rung 16
LD Run_Motor_Up_12  ; Run Up Motor (S12)
OR Run_Motor_Up_20  ; Run Up Motor (S20)
ANDNOT Fault_Initialize  ; Fault - Initialize
ANDNOT Fault_Motor_Up  ; Fault - Motor Up
OUT O_01  ; Up Motor

### Section Faults

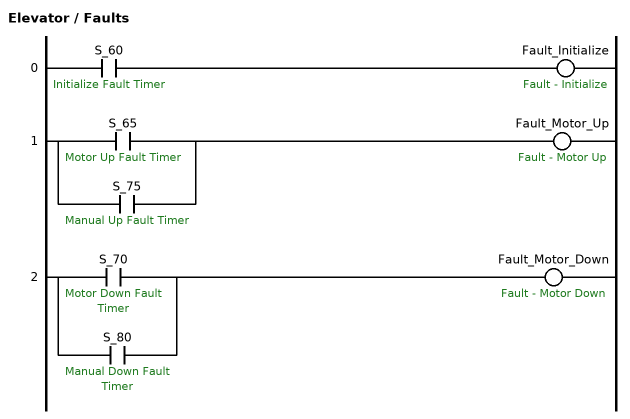
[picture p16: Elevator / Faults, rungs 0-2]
; rung 0
LD S_60  ; Initialize Fault Timer
OUT Fault_Initialize  ; Fault - Initialize
; rung 1
LD S_65  ; Motor Up Fault Timer
OR S_75  ; Manual Up Fault Timer
OUT Fault_Motor_Up  ; Fault - Motor Up
; rung 2
LD S_70  ; Motor Down Fault Timer
OR S_80  ; Manual Down Fault Timer
OUT Fault_Motor_Down  ; Fault - Motor Down

### Section HMI

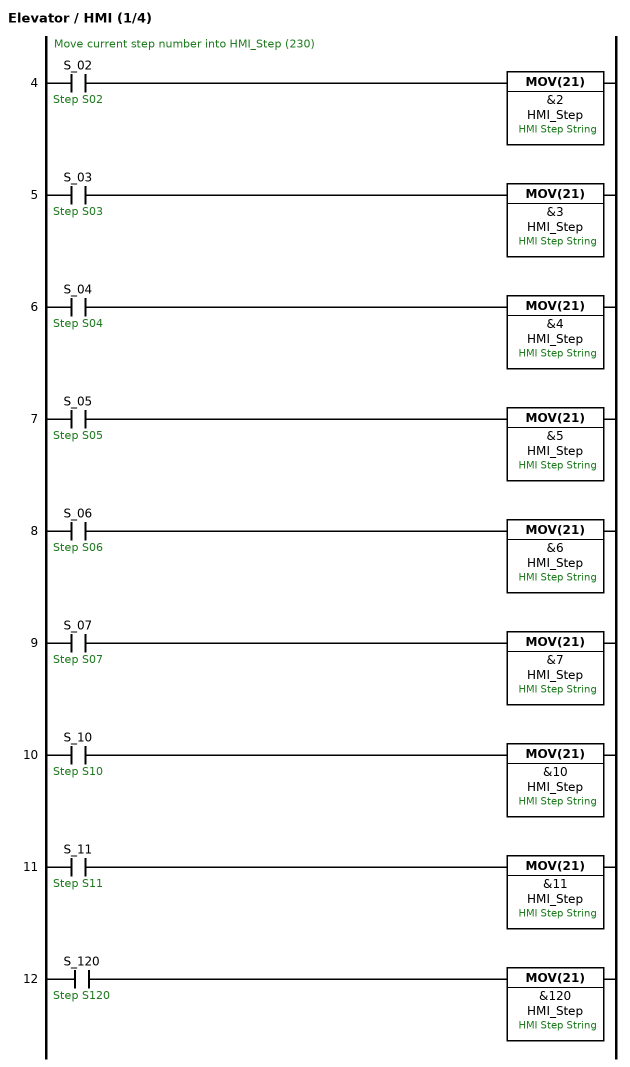
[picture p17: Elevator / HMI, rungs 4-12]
; rung 4: Move current step number into HMI_Step (230)
LD S_02  ; Step S02
MOV(21) &2 HMI_Step  ; HMI Step String
; rung 5
LD S_03  ; Step S03
MOV(21) &3 HMI_Step  ; HMI Step String
; rung 6
LD S_04  ; Step S04
MOV(21) &4 HMI_Step  ; HMI Step String
; rung 7
LD S_05  ; Step S05
MOV(21) &5 HMI_Step  ; HMI Step String
; rung 8
LD S_06  ; Step S06
MOV(21) &6 HMI_Step  ; HMI Step String
; rung 9
LD S_07  ; Step S07
MOV(21) &7 HMI_Step  ; HMI Step String
; rung 10
LD S_10  ; Step S10
MOV(21) &10 HMI_Step  ; HMI Step String
; rung 11
LD S_11  ; Step S11
MOV(21) &11 HMI_Step  ; HMI Step String
; rung 12
LD S_120  ; Step S120
MOV(21) &120 HMI_Step  ; HMI Step String

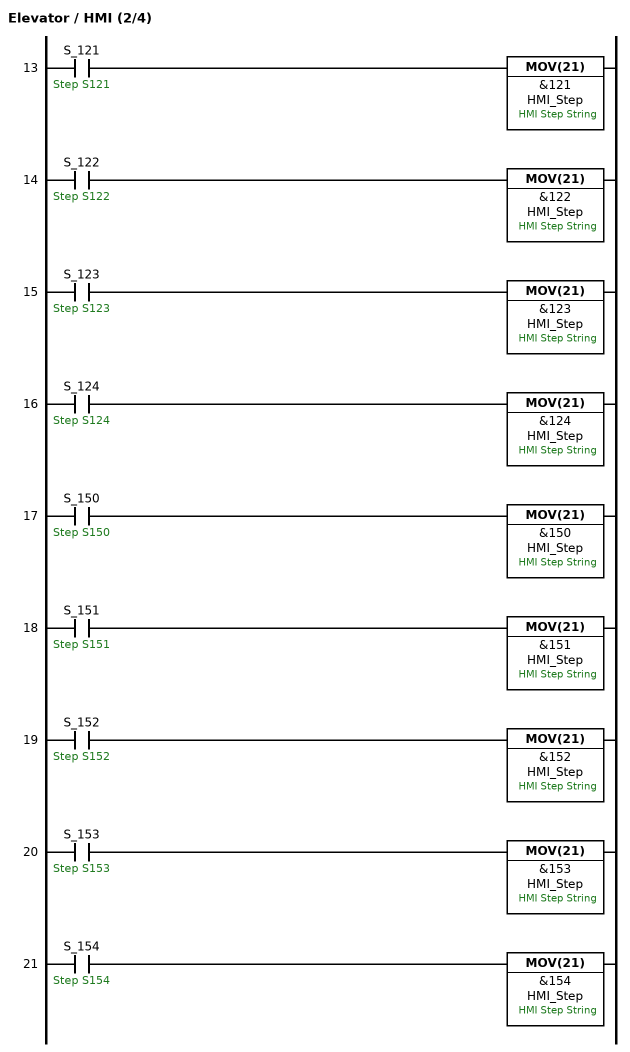
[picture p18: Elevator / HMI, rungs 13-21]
; rung 13
LD S_121  ; Step S121
MOV(21) &121 HMI_Step  ; HMI Step String
; rung 14
LD S_122  ; Step S122
MOV(21) &122 HMI_Step  ; HMI Step String
; rung 15
LD S_123  ; Step S123
MOV(21) &123 HMI_Step  ; HMI Step String
; rung 16
LD S_124  ; Step S124
MOV(21) &124 HMI_Step  ; HMI Step String
; rung 17
LD S_150  ; Step S150
MOV(21) &150 HMI_Step  ; HMI Step String
; rung 18
LD S_151  ; Step S151
MOV(21) &151 HMI_Step  ; HMI Step String
; rung 19
LD S_152  ; Step S152
MOV(21) &152 HMI_Step  ; HMI Step String
; rung 20
LD S_153  ; Step S153
MOV(21) &153 HMI_Step  ; HMI Step String
; rung 21
LD S_154  ; Step S154
MOV(21) &154 HMI_Step  ; HMI Step String

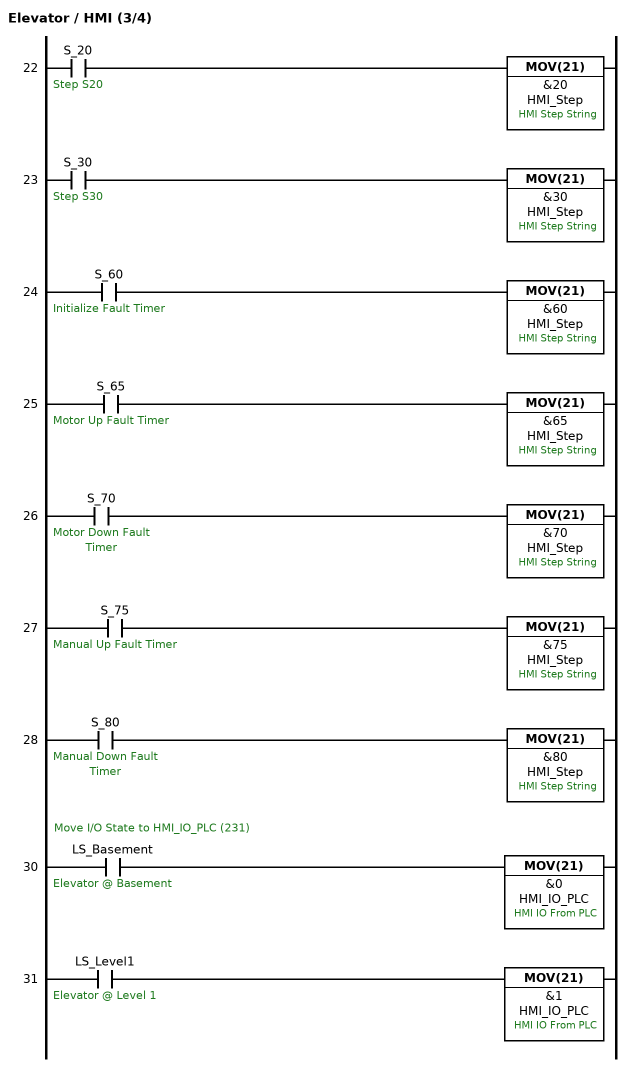
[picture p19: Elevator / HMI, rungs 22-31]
; rung 22
LD S_20  ; Step S20
MOV(21) &20 HMI_Step  ; HMI Step String
; rung 23
LD S_30  ; Step S30
MOV(21) &30 HMI_Step  ; HMI Step String
; rung 24
LD S_60  ; Initialize Fault Timer
MOV(21) &60 HMI_Step  ; HMI Step String
; rung 25
LD S_65  ; Motor Up Fault Timer
MOV(21) &65 HMI_Step  ; HMI Step String
; rung 26
LD S_70  ; Motor Down Fault Timer
MOV(21) &70 HMI_Step  ; HMI Step String
; rung 27
LD S_75  ; Manual Up Fault Timer
MOV(21) &75 HMI_Step  ; HMI Step String
; rung 28
LD S_80  ; Manual Down Fault Timer
MOV(21) &80 HMI_Step  ; HMI Step String
; rung 30: Move I/O State to HMI_IO_PLC (231)
LD LS_Basement  ; Elevator @ Basement
MOV(21) &0 HMI_IO_PLC  ; HMI IO From PLC
; rung 31
LD LS_Level1  ; Elevator @ Level 1
MOV(21) &1 HMI_IO_PLC  ; HMI IO From PLC

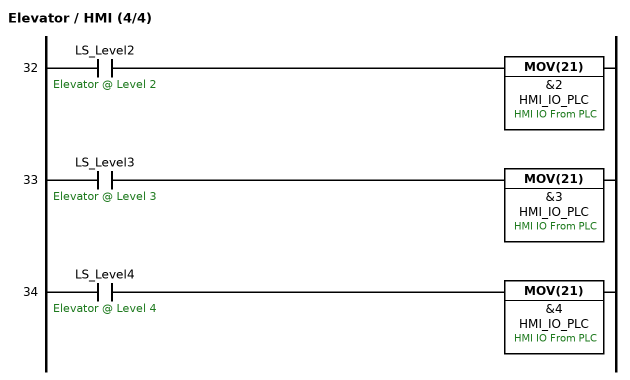
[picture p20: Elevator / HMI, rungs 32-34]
; rung 32
LD LS_Level2  ; Elevator @ Level 2
MOV(21) &2 HMI_IO_PLC  ; HMI IO From PLC
; rung 33
LD LS_Level3  ; Elevator @ Level 3
MOV(21) &3 HMI_IO_PLC  ; HMI IO From PLC
; rung 34
LD LS_Level4  ; Elevator @ Level 4
MOV(21) &4 HMI_IO_PLC  ; HMI IO From PLC
; rung 35: Move I/O State from SCADA (PC)  to HMI_IO_PC (232)

### Section END
; rung 0
END(01)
